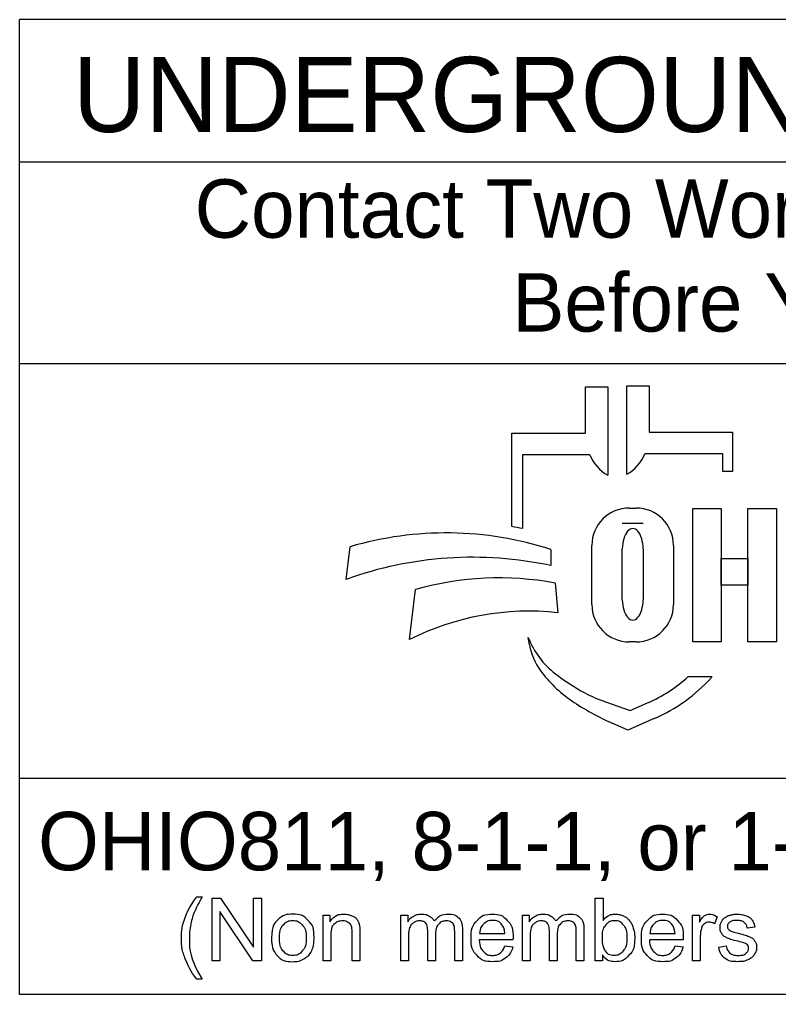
# Model space of a CAD drawing. Extents: x 0 to 45.4, y -2.2 to 22.
# Drawn here: x 2.978 to 4.796, y 2.143 to 4.48 of the extents above; entities that cross this region are included whole.
import ezdxf

# ---------------------------------------------------------------- set-up
doc = ezdxf.new("R2010")
doc.units = 0
doc.layers.add('SH_Data', color=7, linetype='Continuous')
doc.layers.add('SH_Text', color=7, linetype='Continuous')

msp = doc.modelspace()

# ---------------------------------------------------------------- linework, layer by layer
at = {"layer": 'SH_Data'}
for p, q in [((2.9775, 2.1428), (2.9775, 4.4803)), ((7.2275, 4.4803), (2.9775, 4.4803)), ((2.9775, 4.1387), (7.2275, 4.1387)), ((2.9775, 3.6553), (7.2275, 3.6553)), ((7.2275, 2.6607), (2.9775, 2.6607)), ((7.2275, 2.1428), (2.9775, 2.1428))]:
    msp.add_line(p, q, dxfattribs=at)
at = {"layer": 'SH_Text'}
for p, q in [((4.3335, 3.4883), (4.3335, 3.5998)), ((4.3335, 3.5998), (4.3872, 3.5998)), ((4.3872, 3.5998), (4.3872, 3.3877)), ((4.4329, 3.39), (4.4329, 3.6021)), ((4.4329, 3.6021), (4.4865, 3.6021)), ((4.4865, 3.6021), (4.4865, 3.4906)), ((4.1576, 3.2644), (4.1576, 3.4883)), ((4.1576, 3.4883), (4.3335, 3.4883)), ((4.4865, 3.4906), (4.6857, 3.4906)), ((4.6857, 3.4906), (4.6857, 3.3968)), ((4.1828, 3.4369), (4.1828, 3.26)), ((4.3439, 3.4369), (4.1828, 3.4369)), ((4.6625, 3.4392), (4.4761, 3.4392)), ((4.6625, 3.3968), (4.6625, 3.4392)), ((4.6857, 3.3968), (4.6625, 3.3968)), ((4.4385, 3.3091), (4.4551, 3.3091)), ((4.4718, 3.2721), (4.422, 3.2721)), ((3.7602, 3.1381), (3.7696, 3.2162)), ((4.2509, 3.2097), (4.2509, 3.1709)), ((4.3491, 3.0776), (4.3491, 3.2196)), ((4.422, 3.089), (4.422, 3.2114)), ((4.4718, 3.2114), (4.4718, 3.089)), ((4.5445, 3.2196), (4.5445, 3.0776)), ((3.912, 2.9936), (3.9267, 3.1137)), ((4.2608, 3.1291), (4.2671, 3.0582)), ((4.1997, 2.9807), (4.1967, 2.9986)), ((4.4551, 2.9882), (4.4385, 2.9882)), ((4.58, 2.9048), (4.6375, 2.9048)), ((4.3816, 2.8444), (4.441, 2.8239)), ((4.441, 2.8239), (4.4821, 2.8417)), ((4.435, 2.7769), (4.3976, 2.7934)), ((4.4983, 2.8044), (4.435, 2.7769))]:
    msp.add_line(p, q, dxfattribs=at)
for points in [[(4.591, 3.3081), (4.6589, 3.3081), (4.6589, 2.9881), (4.591, 2.9881)], [(4.7231, 3.3081), (4.7911, 3.3081), (4.7911, 2.9881), (4.7231, 2.9881)], [(4.6589, 3.1882), (4.7231, 3.1882), (4.7231, 3.1242), (4.6589, 3.1242)]]:
    msp.add_lwpolyline(points, close=True, dxfattribs=at)
for points in [[(3.4021, 2.3766), (3.4153, 2.3766)], [(3.4389, 2.2239), (3.4389, 2.3741), (3.4592, 2.3741), (3.5382, 2.2561), (3.5382, 2.3741), (3.5572, 2.3741), (3.5572, 2.2239), (3.5369, 2.2239), (3.4579, 2.3419), (3.4579, 2.2239), (3.4389, 2.2239)], [(4.3743, 2.2239), (4.3573, 2.2239), (4.3573, 2.3741), (4.3757, 2.3741), (4.3757, 2.3206)], [(3.7048, 2.2239), (3.7048, 2.3328), (3.7214, 2.3328), (3.7214, 2.3173)], [(3.8912, 2.2239), (3.8912, 2.3328), (3.9077, 2.3328), (3.9077, 2.3174)], [(4.1826, 2.2239), (4.1826, 2.3328), (4.1991, 2.3328), (4.1991, 2.3174)], [(4.5904, 2.2239), (4.5904, 2.3328), (4.607, 2.3328), (4.607, 2.3163)], [(4.6495, 2.3293), (4.643, 2.3122)], [(3.7932, 2.2908), (3.7932, 2.2239), (3.7748, 2.2239), (3.7748, 2.2901)], [(3.9743, 2.2871), (3.9743, 2.2239), (3.9559, 2.2239), (3.9559, 2.2946)], [(4.0388, 2.2986), (4.0388, 2.2239), (4.0203, 2.2239), (4.0203, 2.2924)], [(4.2657, 2.2871), (4.2657, 2.2239), (4.2473, 2.2239), (4.2473, 2.2946)], [(4.3301, 2.2986), (4.3301, 2.2239), (4.3117, 2.2239), (4.3117, 2.2924)], [(4.7394, 2.3046), (4.7213, 2.3022)], [(3.7233, 2.2833), (3.7233, 2.2239), (3.7048, 2.2239)], [(3.9097, 2.2803), (3.9097, 2.2239), (3.8912, 2.2239)], [(4.16, 2.2736), (4.0788, 2.2736)], [(4.0799, 2.2887), (4.1406, 2.2887)], [(4.201, 2.2803), (4.201, 2.2239), (4.1826, 2.2239)], [(4.568, 2.2736), (4.4868, 2.2736)], [(4.4879, 2.2887), (4.5486, 2.2887)], [(4.6088, 2.2809), (4.6088, 2.2239), (4.5904, 2.2239)], [(4.1404, 2.2591), (4.1595, 2.2567)], [(4.5484, 2.2591), (4.5675, 2.2567)], [(4.653, 2.2564), (4.6712, 2.2593)], [(4.3743, 2.2375), (4.3743, 2.2239)], [(3.4153, 2.1798), (3.4021, 2.1798)]]:
    msp.add_lwpolyline(points, dxfattribs=at)
for centre, radius, start, end in [((4.4353, 3.4736), 0.0985, 201.9296, 240.7469), ((4.3847, 3.476), 0.0985, 299.2531, 338.0704), ((4.4385, 3.2196), 0.0895, 90, 180), ((4.4551, 3.2196), 0.0895, 0, 90), ((3.9997, 2.4302), 0.8191, 72.1402, 106.3144), ((4.0295, 2.4554), 0.8191, 79.2074, 81.0007), ((4.0628, 2.2991), 0.8919, 77.8238, 109.8274), ((4.1267, 2.4094), 0.7322, 79.44, 105.8467), ((4.4385, 3.0776), 0.0895, 180, 270), ((4.4551, 3.0776), 0.0895, 270, 0), ((4.1987, 2.4262), 0.6357, 83.8248, 116.8021), ((4.3841, 3.0707), 0.2008, 201.0457, 232.5314), ((4.341, 3.0048), 0.1433, 189.6817, 216.0884), ((4.4747, 3.1022), 0.3088, 216.0884, 235.7167), ((4.5766, 3.3219), 0.5173, 232.5314, 241.794), ((4.3387, 3.1722), 0.3602, 293.4582, 312.0712), ((4.3387, 3.1722), 0.401, 293.4582, 317.8286), ((4.4914, 3.1631), 0.3371, 241.794, 250.9821), ((4.6412, 3.3465), 0.6044, 235.7167, 246.2325)]:
    msp.add_arc(centre, radius, start, end, dxfattribs=at)
for centre, start_param, end_param in [((4.4469, 3.2114), 4.712389, 7.853982), ((4.4469, 3.089), 1.570796, 4.712389)]:
    msp.add_ellipse(centre, major_axis=(0, 0.0484), ratio=0.514403, start_param=start_param, end_param=end_param, dxfattribs=at)
for points in [[(3.4021, 2.1798), (3.3869, 2.199), (3.3763, 2.2248), (3.3657, 2.2506), (3.3657, 2.2783), (3.3657, 2.3026), (3.3736, 2.325), (3.3829, 2.3509), (3.4021, 2.3766)], [(3.4153, 2.3766), (3.4029, 2.3553), (3.3989, 2.3462), (3.3927, 2.332), (3.3891, 2.3167), (3.3847, 2.2975), (3.3847, 2.2782), (3.3847, 2.2289), (3.4153, 2.1798)], [(3.5814, 2.2783), (3.5814, 2.3085), (3.5981, 2.3231), (3.6122, 2.3352), (3.6323, 2.3352), (3.6547, 2.3352), (3.669, 2.3205), (3.6832, 2.3058), (3.6832, 2.2799), (3.6832, 2.2589), (3.6769, 2.2469), (3.6706, 2.2348), (3.6586, 2.2282), (3.6466, 2.2215), (3.6323, 2.2215), (3.6095, 2.2215), (3.5954, 2.2362), (3.5814, 2.2508), (3.5814, 2.2783)], [(3.6003, 2.2783), (3.6003, 2.2574), (3.6094, 2.247), (3.6185, 2.2366), (3.6323, 2.2366), (3.646, 2.2366), (3.6551, 2.2471), (3.6642, 2.2575), (3.6642, 2.279), (3.6642, 2.2991), (3.6551, 2.3095), (3.6459, 2.3199), (3.6323, 2.3199), (3.6185, 2.3199), (3.6094, 2.3096), (3.6003, 2.2992), (3.6003, 2.2783)], [(3.7214, 2.3173), (3.7334, 2.3352), (3.756, 2.3352), (3.7659, 2.3352), (3.7741, 2.3316), (3.7823, 2.3281), (3.7864, 2.3224), (3.7905, 2.3166), (3.7922, 2.3087), (3.7932, 2.3036), (3.7932, 2.2908)], [(3.7748, 2.2901), (3.7748, 2.3013), (3.7726, 2.3069), (3.7705, 2.3125), (3.765, 2.3158), (3.7595, 2.3191), (3.7521, 2.3191), (3.7404, 2.3191), (3.7318, 2.3117), (3.7233, 2.3042), (3.7233, 2.2833)], [(3.9077, 2.3174), (3.9128, 2.3254), (3.9214, 2.3303), (3.9299, 2.3352), (3.9407, 2.3352), (3.9528, 2.3352), (3.9606, 2.3301), (3.9683, 2.3251), (3.9715, 2.3161), (3.9844, 2.3352), (4.0051, 2.3352), (4.0213, 2.3352), (4.03, 2.3262), (4.0388, 2.3172), (4.0388, 2.2986)], [(3.9559, 2.2946), (3.9559, 2.3069), (3.9514, 2.313), (3.9469, 2.3191), (3.9366, 2.3191), (3.9288, 2.3191), (3.9222, 2.315), (3.9156, 2.311), (3.9126, 2.3031), (3.9097, 2.2952), (3.9097, 2.2803)], [(4.0203, 2.2924), (4.0203, 2.3035), (4.0185, 2.3083), (4.0168, 2.3132), (4.012, 2.3162), (4.0073, 2.3191), (4.001, 2.3191), (3.9895, 2.3191), (3.9819, 2.3115), (3.9743, 2.3039), (3.9743, 2.2871)], [(4.1595, 2.2567), (4.155, 2.24), (4.1428, 2.2307), (4.1306, 2.2215), (4.1117, 2.2215), (4.0878, 2.2215), (4.0738, 2.2362), (4.0598, 2.2509), (4.0598, 2.2774), (4.0598, 2.3049), (4.074, 2.32), (4.0881, 2.3352), (4.1106, 2.3352), (4.1324, 2.3352), (4.1463, 2.3203), (4.1601, 2.3055), (4.1601, 2.2785), (4.1601, 2.2769), (4.16, 2.2736)], [(4.1406, 2.2887), (4.1394, 2.3025), (4.1337, 2.3094), (4.1249, 2.3201), (4.1108, 2.3201), (4.0981, 2.3201), (4.0894, 2.3115), (4.0808, 2.303), (4.0799, 2.2887)], [(4.1991, 2.3174), (4.2042, 2.3254), (4.2127, 2.3303), (4.2212, 2.3352), (4.2321, 2.3352), (4.2442, 2.3352), (4.2519, 2.3301), (4.2597, 2.3251), (4.2628, 2.3161), (4.2758, 2.3352), (4.2965, 2.3352), (4.3127, 2.3352), (4.3214, 2.3262), (4.3301, 2.3172), (4.3301, 2.2986)], [(4.2473, 2.2946), (4.2473, 2.3069), (4.2428, 2.313), (4.2383, 2.3191), (4.228, 2.3191), (4.2202, 2.3191), (4.2136, 2.315), (4.207, 2.311), (4.204, 2.3031), (4.201, 2.2952), (4.201, 2.2803)], [(4.3117, 2.2924), (4.3117, 2.3035), (4.3099, 2.3083), (4.3081, 2.3132), (4.3034, 2.3162), (4.2987, 2.3191), (4.2923, 2.3191), (4.2809, 2.3191), (4.2733, 2.3115), (4.2657, 2.3039), (4.2657, 2.2871)], [(4.3741, 2.2792), (4.3741, 2.2596), (4.3794, 2.2509), (4.3881, 2.2366), (4.4029, 2.2366), (4.415, 2.2366), (4.4238, 2.2471), (4.4326, 2.2576), (4.4326, 2.2784), (4.4326, 2.2998), (4.4241, 2.3099), (4.4157, 2.3201), (4.4038, 2.3201), (4.3917, 2.3201), (4.3829, 2.3096), (4.3741, 2.299), (4.3741, 2.2792)], [(4.3757, 2.3206), (4.3874, 2.3352), (4.4055, 2.3352), (4.4155, 2.3352), (4.4245, 2.3311), (4.4335, 2.3271), (4.4392, 2.3198), (4.445, 2.3124), (4.4483, 2.3021), (4.4516, 2.2918), (4.4516, 2.28), (4.4516, 2.252), (4.4378, 2.2368), (4.4239, 2.2215), (4.4046, 2.2215), (4.3853, 2.2215), (4.3743, 2.2375)], [(4.5675, 2.2567), (4.563, 2.24), (4.5508, 2.2307), (4.5386, 2.2215), (4.5196, 2.2215), (4.4958, 2.2215), (4.4818, 2.2362), (4.4678, 2.2509), (4.4678, 2.2774), (4.4678, 2.3049), (4.482, 2.32), (4.4961, 2.3352), (4.5186, 2.3352), (4.5404, 2.3352), (4.5543, 2.3203), (4.5681, 2.3055), (4.5681, 2.2785), (4.5681, 2.2769), (4.568, 2.2736)], [(4.5486, 2.2887), (4.5474, 2.3025), (4.5417, 2.3094), (4.5328, 2.3201), (4.5188, 2.3201), (4.5061, 2.3201), (4.4974, 2.3115), (4.4888, 2.303), (4.4879, 2.2887)], [(4.607, 2.3163), (4.6133, 2.3278), (4.6187, 2.3315), (4.6241, 2.3352), (4.6305, 2.3352), (4.6398, 2.3352), (4.6495, 2.3293)], [(4.643, 2.3122), (4.6363, 2.3162), (4.6295, 2.3162), (4.6235, 2.3162), (4.6187, 2.3125), (4.6139, 2.3089), (4.6119, 2.3024), (4.6088, 2.2926), (4.6088, 2.2809)], [(4.7213, 2.3022), (4.7201, 2.3106), (4.7142, 2.3153), (4.7083, 2.3201), (4.6975, 2.3201), (4.6848, 2.3201), (4.6794, 2.3159), (4.6739, 2.3116), (4.6739, 2.306), (4.6739, 2.3024), (4.6762, 2.2995), (4.6785, 2.2966), (4.6833, 2.2946), (4.686, 2.2936), (4.6996, 2.2899), (4.7192, 2.2847), (4.7269, 2.2813), (4.7347, 2.278), (4.7391, 2.2717), (4.7435, 2.2653), (4.7435, 2.2559), (4.7435, 2.2467), (4.7381, 2.2386), (4.7327, 2.2304), (4.7226, 2.226), (4.7124, 2.2215), (4.6996, 2.2215), (4.6784, 2.2215), (4.6672, 2.2303), (4.6561, 2.2391), (4.653, 2.2564)], [(4.6712, 2.2593), (4.6727, 2.2483), (4.6798, 2.2425), (4.6868, 2.2366), (4.6995, 2.2366), (4.7122, 2.2366), (4.7184, 2.2418), (4.7245, 2.247), (4.7245, 2.254), (4.7245, 2.2602), (4.7191, 2.2638), (4.7153, 2.2663), (4.7002, 2.2701), (4.6799, 2.2752), (4.672, 2.2789), (4.6642, 2.2827), (4.6601, 2.2893), (4.6561, 2.2959), (4.6561, 2.3038), (4.6561, 2.3111), (4.6594, 2.3173), (4.6628, 2.3235), (4.6685, 2.3276), (4.6728, 2.3308), (4.6803, 2.333), (4.6877, 2.3352), (4.6962, 2.3352), (4.709, 2.3352), (4.7187, 2.3315), (4.7284, 2.3278), (4.733, 2.3215), (4.7377, 2.3152), (4.7394, 2.3046)], [(4.0788, 2.2736), (4.0799, 2.2557), (4.089, 2.2462), (4.0981, 2.2366), (4.1117, 2.2366), (4.1219, 2.2366), (4.1291, 2.242), (4.1362, 2.2473), (4.1404, 2.2591)], [(4.4868, 2.2736), (4.4879, 2.2557), (4.497, 2.2462), (4.5061, 2.2366), (4.5197, 2.2366), (4.5299, 2.2366), (4.537, 2.242), (4.5442, 2.2473), (4.5484, 2.2591)]]:
    msp.add_open_spline(points, degree=3, dxfattribs=at)

# ---------------------------------------------------------------- texts
for s, height, p in [('UNDERGROUND UTILITIES', 0.18, (3.1057, 4.2106)), ('Contact Two Working Days', 0.14, (3.3972, 3.9571)), ('Before You Dig', 0.14, (4.1583, 3.7321)), ('OHIO811, 8-1-1, or 1-800-362-2764', 0.14, (3.022, 2.4406))]:
    msp.add_text(s, height=height, dxfattribs=at).set_placement(p)

doc.saveas('drawing.dxf')
